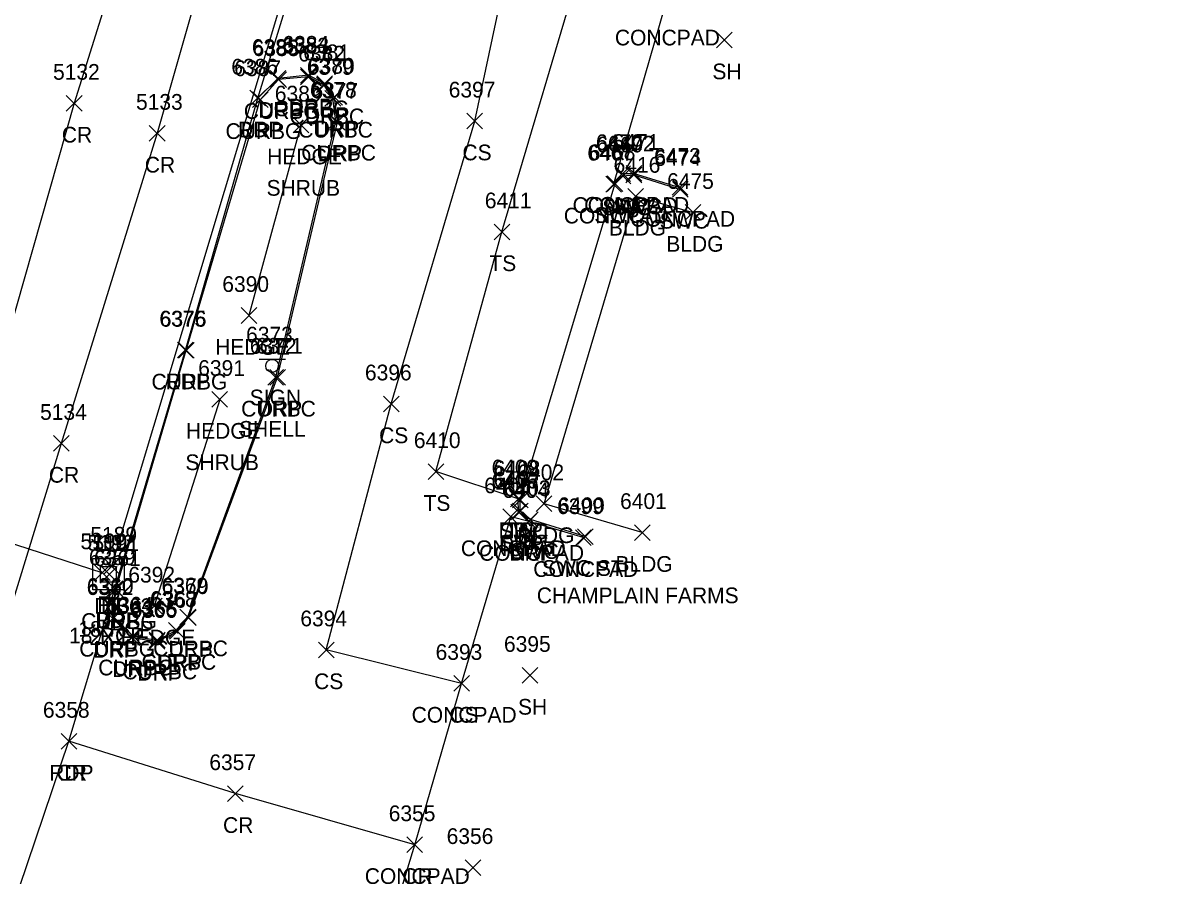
# Model space of a CAD drawing. Extents: x 1462089 to 1464015, y 730534 to 736144.
# Drawn here: x 1462606.1 to 1462752.9, y 731296.2 to 731404.8 of the extents above; entities that cross this region are included whole.
import ezdxf

# ---------------------------------------------------------------- set-up
doc = ezdxf.new("R2010")
doc.units = 0
for name, color, linetype in [('D_A', 7, 'Continuous'), ('D_C', 7, 'Continuous'), ('D_I', 7, 'Continuous'), ('D_TIC', 7, 'Continuous'), ('DCP', 7, 'Continuous'), ('DS', 7, 'Continuous'), ('L_A', 7, 'Continuous'), ('L_C', 7, 'Continuous'), ('L_I', 7, 'Continuous'), ('L_TIC', 7, 'Continuous'), ('LAHR', 7, 'Continuous'), ('LBC', 7, 'Continuous'), ('LELB', 7, 'Continuous'), ('LS', 7, 'Continuous'), ('P_A', 7, 'Continuous'), ('P_I', 7, 'Continuous'), ('P_TIC', 7, 'Continuous'), ('PET', 7, 'Continuous'), ('PRC', 7, 'Continuous'), ('R_A', 7, 'Continuous'), ('R_I', 7, 'Continuous'), ('R_TIC', 7, 'Continuous'), ('RC', 7, 'Continuous'), ('RDP', 7, 'Continuous'), ('RSW', 7, 'Continuous'), ('S_A', 7, 'Continuous'), ('S_C', 7, 'Continuous'), ('S_I', 7, 'Continuous'), ('SSGN', 7, 'Continuous')]:
    doc.layers.add(name, color=color, linetype=linetype)

msp = doc.modelspace()

# ---------------------------------------------------------------- linework, layer by layer
at = {"layer": 'D_TIC'}
for points in [[(1462615.15, 731333.76), (1462617.15, 731335.76)], [(1462617.15, 731333.76), (1462615.15, 731335.76)], [(1462616.03, 731333.54), (1462618.03, 731335.54)], [(1462618.03, 731333.54), (1462616.03, 731335.54)], [(1462616.33, 731334.6), (1462618.33, 731336.6)], [(1462618.33, 731334.6), (1462616.33, 731336.6)]]:
    msp.add_lwpolyline(points, dxfattribs=at)
at = {"layer": 'DCP'}
for points in [[(1462656.86, 731467.04), (1462617.33, 731335.6)], [(1462616.15, 731334.76), (1462550.47, 731356.02)]]:
    msp.add_lwpolyline(points, dxfattribs=at)
at = {"layer": 'DS'}
for p, q in [((1462614.94, 731336.57), (1462618.94, 731336.57)), ((1462614.94, 731332.57), (1462614.94, 731336.57)), ((1462615.94, 731333.57), (1462615.94, 731335.57)), ((1462615.94, 731335.57), (1462617.94, 731335.57)), ((1462617.94, 731335.57), (1462617.94, 731333.57)), ((1462618.94, 731336.57), (1462618.94, 731332.57)), ((1462616.95, 731334.57), (1462616.95, 731334.57)), ((1462616.95, 731334.57), (1462616.95, 731334.57)), ((1462618.94, 731332.57), (1462614.94, 731332.57)), ((1462617.94, 731333.57), (1462615.94, 731333.57))]:
    msp.add_line(p, q, dxfattribs=at)
at = {"layer": 'L_TIC'}
for points in [[(1462694.38, 731401.6), (1462696.38, 731403.6)], [(1462696.38, 731401.6), (1462694.38, 731403.6)], [(1462640.45, 731390.77), (1462642.45, 731392.77)], [(1462642.45, 731390.77), (1462640.45, 731392.77)], [(1462662.59, 731391.28), (1462664.59, 731393.28)], [(1462664.59, 731391.28), (1462662.59, 731393.28)], [(1462681.42, 731384.58), (1462683.42, 731386.58)], [(1462683.42, 731384.58), (1462681.42, 731386.58)], [(1462682.9, 731384.61), (1462684.9, 731386.61)], [(1462684.9, 731384.61), (1462682.9, 731386.61)], [(1462680.29, 731383.24), (1462682.29, 731385.24)], [(1462682.29, 731383.24), (1462680.29, 731385.24)], [(1462680.29, 731383.24), (1462682.29, 731385.24)], [(1462682.29, 731383.24), (1462680.29, 731385.24)], [(1462688.74, 731382.83), (1462690.74, 731384.83)], [(1462690.74, 731382.83), (1462688.74, 731384.83)], [(1462683.09, 731381.7), (1462685.09, 731383.7)], [(1462685.09, 731381.7), (1462683.09, 731383.7)], [(1462690.41, 731379.64), (1462692.41, 731381.64)], [(1462692.41, 731379.64), (1462690.41, 731381.64)], [(1462666.05, 731377.17), (1462668.05, 731379.17)], [(1462668.05, 731377.17), (1462666.05, 731379.17)], [(1462633.83, 731366.52), (1462635.83, 731368.52)], [(1462635.83, 731366.52), (1462633.83, 731368.52)], [(1462630.11, 731355.83), (1462632.11, 731357.83)], [(1462632.11, 731355.83), (1462630.11, 731357.83)], [(1462651.97, 731355.26), (1462653.97, 731357.26)], [(1462653.97, 731355.26), (1462651.97, 731357.26)], [(1462657.66, 731346.64), (1462659.66, 731348.64)], [(1462659.66, 731346.64), (1462657.66, 731348.64)], [(1462668.13, 731343.16), (1462670.13, 731345.16)], [(1462670.13, 731343.16), (1462668.13, 731345.16)], [(1462671.42, 731342.54), (1462673.42, 731344.54)], [(1462673.42, 731342.54), (1462671.42, 731344.54)], [(1462667.18, 731340.88), (1462669.18, 731342.88)], [(1462669.18, 731340.88), (1462667.18, 731342.88)], [(1462667.18, 731340.88), (1462669.18, 731342.88)], [(1462669.18, 731340.88), (1462667.18, 731342.88)], [(1462669.51, 731340.29), (1462671.51, 731342.29)], [(1462671.51, 731340.29), (1462669.51, 731342.29)], [(1462676.41, 731338.23), (1462678.41, 731340.23)], [(1462678.41, 731338.23), (1462676.41, 731340.23)], [(1462683.93, 731338.88), (1462685.93, 731340.88)], [(1462685.93, 731338.88), (1462683.93, 731340.88)], [(1462621.77, 731329.51), (1462623.77, 731331.51)], [(1462623.77, 731329.51), (1462621.77, 731331.51)], [(1462643.69, 731323.94), (1462645.69, 731325.94)], [(1462645.69, 731323.94), (1462643.69, 731325.94)], [(1462669.62, 731320.69), (1462671.62, 731322.69)], [(1462671.62, 731320.69), (1462669.62, 731322.69)], [(1462660.92, 731319.67), (1462662.92, 731321.67)], [(1462662.92, 731319.67), (1462660.92, 731321.67)], [(1462660.92, 731319.67), (1462662.92, 731321.67)], [(1462662.92, 731319.67), (1462660.92, 731321.67)], [(1462654.95, 731299.13), (1462656.95, 731301.13)], [(1462656.95, 731299.13), (1462654.95, 731301.13)], [(1462662.38, 731296.22), (1462664.38, 731298.22)], [(1462664.38, 731296.22), (1462662.38, 731298.22)]]:
    msp.add_lwpolyline(points, dxfattribs=at)
at = {"layer": 'LAHR'}
for points in [[(1462641.45, 731391.77), (1462634.83, 731367.52)], [(1462631.11, 731356.83), (1462622.77, 731330.51)]]:
    msp.add_lwpolyline(points, dxfattribs=at)
at = {"layer": 'LBC'}
msp.add_lwpolyline([(1462684.93, 731339.88), (1462672.42, 731343.54), (1462684.09, 731382.7), (1462691.41, 731380.64)], dxfattribs=at)
at = {"layer": 'LELB'}
for points in [[(1462669.13, 731344.16), (1462658.66, 731347.64), (1462667.05, 731378.17), (1462677.7, 731414.12), (1462689.25, 731456.08)], [(1462661.92, 731320.67), (1462644.69, 731324.94), (1462652.97, 731356.26), (1462663.59, 731392.28), (1462668.66, 731416.05), (1462674.24, 731446.96)]]:
    msp.add_lwpolyline(points, dxfattribs=at)
at = {"layer": 'LS'}
for points in [[(1462687.8, 731406.91), (1462681.29, 731384.24)], [(1462681.29, 731384.24), (1462682.42, 731385.58), (1462683.9, 731385.61), (1462689.74, 731383.83)], [(1462661.6, 731283.5), (1462651.86, 731286.58), (1462655.95, 731300.13), (1462661.92, 731320.67), (1462668.18, 731341.88)], [(1462677.41, 731339.23), (1462670.51, 731341.29), (1462668.18, 731341.88)]]:
    msp.add_lwpolyline(points, dxfattribs=at)
at = {"layer": 'P_TIC'}
for points in [[(1462634.96, 731394.2), (1462636.96, 731396.2)], [(1462636.96, 731394.2), (1462634.96, 731396.2)], [(1462611.57, 731393.54), (1462613.57, 731395.54)], [(1462613.57, 731393.54), (1462611.57, 731395.54)], [(1462622.14, 731389.72), (1462624.14, 731391.72)], [(1462624.14, 731389.72), (1462622.14, 731391.72)], [(1462625.73, 731362.12), (1462627.73, 731364.12)], [(1462627.73, 731362.12), (1462625.73, 731364.12)], [(1462609.92, 731350.23), (1462611.92, 731352.23)], [(1462611.92, 731350.23), (1462609.92, 731352.23)], [(1462616.75, 731331.74), (1462618.75, 731333.74)], [(1462618.75, 731331.74), (1462616.75, 731333.74)], [(1462610.9, 731312.3), (1462612.9, 731314.3)], [(1462612.9, 731312.3), (1462610.9, 731314.3)], [(1462610.9, 731312.3), (1462612.9, 731314.3)], [(1462612.9, 731312.3), (1462610.9, 731314.3)], [(1462632.1, 731305.63), (1462634.1, 731307.63)], [(1462634.1, 731305.63), (1462632.1, 731307.63)], [(1462654.95, 731299.13), (1462656.95, 731301.13)], [(1462656.95, 731299.13), (1462654.95, 731301.13)]]:
    msp.add_lwpolyline(points, dxfattribs=at)
at = {"layer": 'PET'}
msp.add_lwpolyline([(1462581.47, 731216.16), (1462595.42, 731259.35), (1462601.33, 731282.14), (1462611.9, 731313.3), (1462617.75, 731332.74), (1462626.73, 731363.12), (1462635.96, 731395.2), (1462650.7, 731443.13), (1462658.25, 731467.85), (1462666.38, 731494.9), (1462678.49, 731533.96), (1462682, 731542.57), (1462703.33, 731606.12), (1462712.89, 731635.26), (1462724.51, 731674.81), (1462732.57, 731701.31), (1462734.12, 731706.18), (1462734.47, 731705.73), (1462745.24, 731743.48), (1462759.09, 731789.57)], dxfattribs=at)
at = {"layer": 'PRC'}
for points in [[(1462782.02, 731950.47), (1462768.89, 731909.84), (1462760.03, 731877.27), (1462749.82, 731847.72), (1462735.79, 731799.64), (1462732.29, 731789.16), (1462718.71, 731743.61), (1462707.11, 731705.53), (1462694.32, 731660.71), (1462680.69, 731618.48), (1462665.7, 731575.68), (1462653.41, 731528.21), (1462637.72, 731478.42), (1462624.25, 731431.84), (1462612.57, 731394.54), (1462600.92, 731353.76), (1462584.46, 731303.13), (1462565.79, 731242.26), (1462548.64, 731186.3), (1462531.51, 731132.98), (1462517.28, 731085.28)], [(1462793.02, 731947.65), (1462779.18, 731905.95), (1462772.13, 731874.55), (1462759.59, 731843.4), (1462745.8, 731796.52), (1462742.09, 731785.85), (1462729.2, 731739.31), (1462722.15, 731715.56), (1462711.04, 731679.92), (1462704.9, 731658.03), (1462690.28, 731612.58), (1462677.1, 731571.22), (1462663.07, 731525.56), (1462648.8, 731477.5), (1462634.52, 731430.68), (1462623.14, 731390.72), (1462610.92, 731351.23), (1462594.7, 731298.49), (1462575.73, 731238.98), (1462558.6, 731184.66), (1462539.6, 731135.54), (1462521.54, 731083.73), (1462509.35, 731045.03)], [(1462655.95, 731300.13), (1462633.1, 731306.63), (1462611.9, 731313.3)]]:
    msp.add_lwpolyline(points, dxfattribs=at)
at = {"layer": 'R_TIC'}
for points in [[(1462637.52, 731396.7), (1462639.52, 731398.7)], [(1462639.52, 731396.7), (1462637.52, 731398.7)], [(1462641.4, 731396.89), (1462643.4, 731398.89)], [(1462643.4, 731396.89), (1462641.4, 731398.89)], [(1462641.41, 731397.11), (1462643.41, 731399.11)], [(1462643.41, 731397.11), (1462641.41, 731399.11)], [(1462637.6, 731396.56), (1462639.6, 731398.56)], [(1462639.6, 731396.56), (1462637.6, 731398.56)], [(1462637.6, 731396.56), (1462639.6, 731398.56)], [(1462639.6, 731396.56), (1462637.6, 731398.56)], [(1462643.42, 731395.87), (1462645.42, 731397.87)], [(1462645.42, 731395.87), (1462643.42, 731397.87)], [(1462643.49, 731396.03), (1462645.49, 731398.03)], [(1462645.49, 731396.03), (1462643.49, 731398.03)], [(1462634.96, 731394.2), (1462636.96, 731396.2)], [(1462636.96, 731394.2), (1462634.96, 731396.2)], [(1462635.27, 731394), (1462637.27, 731396)], [(1462637.27, 731394), (1462635.27, 731396)], [(1462644.52, 731394.17), (1462646.52, 731396.17)], [(1462646.52, 731394.17), (1462644.52, 731396.17)], [(1462644.74, 731394.31), (1462646.74, 731396.31)], [(1462646.74, 731394.31), (1462644.74, 731396.31)], [(1462644.91, 731391.25), (1462646.91, 731393.25)], [(1462646.91, 731391.25), (1462644.91, 731393.25)], [(1462645.1, 731391.14), (1462647.1, 731393.14)], [(1462647.1, 731391.14), (1462645.1, 731393.14)], [(1462681.48, 731384.29), (1462683.48, 731386.29)], [(1462683.48, 731384.29), (1462681.48, 731386.29)], [(1462682.86, 731384.41), (1462684.86, 731386.41)], [(1462684.86, 731384.41), (1462682.86, 731386.41)], [(1462680.47, 731383.31), (1462682.47, 731385.31)], [(1462682.47, 731383.31), (1462680.47, 731385.31)], [(1462688.79, 731382.58), (1462690.79, 731384.58)], [(1462690.79, 731382.58), (1462688.79, 731384.58)], [(1462625.84, 731362.09), (1462627.84, 731364.09)], [(1462627.84, 731362.09), (1462625.84, 731364.09)], [(1462637.25, 731358.65), (1462639.25, 731360.65)], [(1462639.25, 731358.65), (1462637.25, 731360.65)], [(1462637.48, 731358.66), (1462639.48, 731360.66)], [(1462639.48, 731358.66), (1462637.48, 731360.66)], [(1462668.13, 731343.16), (1462670.13, 731345.16)], [(1462670.13, 731343.16), (1462668.13, 731345.16)], [(1462668.39, 731343.04), (1462670.39, 731345.04)], [(1462670.39, 731343.04), (1462668.39, 731345.04)], [(1462668.18, 731341.49), (1462670.18, 731343.49)], [(1462670.18, 731341.49), (1462668.18, 731343.49)], [(1462668.39, 731341.6), (1462670.39, 731343.6)], [(1462670.39, 731341.6), (1462668.39, 731343.6)], [(1462669.51, 731340.29), (1462671.51, 731342.29)], [(1462671.51, 731340.29), (1462669.51, 731342.29)], [(1462669.69, 731340.52), (1462671.69, 731342.52)], [(1462671.69, 731340.52), (1462669.69, 731342.52)], [(1462676.67, 731338.36), (1462678.67, 731340.36)], [(1462678.67, 731338.36), (1462676.67, 731340.36)], [(1462616.75, 731331.74), (1462618.75, 731333.74)], [(1462618.75, 731331.74), (1462616.75, 731333.74)], [(1462616.87, 731331.61), (1462618.87, 731333.61)], [(1462618.87, 731331.61), (1462616.87, 731333.61)], [(1462616.52, 731327.93), (1462618.52, 731329.93)], [(1462618.52, 731327.93), (1462616.52, 731329.93)], [(1462616.64, 731328.08), (1462618.64, 731330.08)], [(1462618.64, 731328.08), (1462616.64, 731330.08)], [(1462616.64, 731328.08), (1462618.64, 731330.08)], [(1462618.64, 731328.08), (1462616.64, 731330.08)], [(1462626.05, 731328.13), (1462628.05, 731330.13)], [(1462628.05, 731328.13), (1462626.05, 731330.13)], [(1462626.12, 731328.05), (1462628.12, 731330.05)], [(1462628.12, 731328.05), (1462626.12, 731330.05)], [(1462624.57, 731326.41), (1462626.57, 731328.41)], [(1462626.57, 731326.41), (1462624.57, 731328.41)], [(1462624.72, 731326.3), (1462626.72, 731328.3)], [(1462626.72, 731326.3), (1462624.72, 731328.3)], [(1462618.92, 731325.5), (1462620.92, 731327.5)], [(1462620.92, 731325.5), (1462618.92, 731327.5)], [(1462619.05, 731325.69), (1462621.05, 731327.69)], [(1462621.05, 731325.69), (1462619.05, 731327.69)], [(1462622.13, 731325.02), (1462624.13, 731327.02)], [(1462624.13, 731325.02), (1462622.13, 731327.02)], [(1462622.14, 731325.19), (1462624.14, 731327.19)], [(1462624.14, 731325.19), (1462622.14, 731327.19)]]:
    msp.add_lwpolyline(points, dxfattribs=at)
at = {"layer": 'RC'}
for points in [[(1462617.64, 731329.08), (1462620.05, 731326.69), (1462623.14, 731326.19), (1462625.57, 731327.41), (1462627.05, 731329.13), (1462638.25, 731359.65), (1462645.91, 731392.25), (1462645.52, 731395.17), (1462644.42, 731396.87), (1462642.4, 731397.89), (1462638.6, 731397.56)], [(1462617.64, 731329.08), (1462617.87, 731332.61), (1462626.84, 731363.09), (1462636.27, 731395), (1462638.6, 731397.56)]]:
    msp.add_lwpolyline(points, dxfattribs=at)
at = {"layer": 'RDP'}
for points in [[(1462617.75, 731332.74), (1462617.52, 731328.93), (1462619.92, 731326.5), (1462623.13, 731326.02), (1462625.72, 731327.3), (1462627.12, 731329.05), (1462638.48, 731359.66), (1462646.1, 731392.14), (1462645.74, 731395.31), (1462644.49, 731397.03), (1462642.41, 731398.11), (1462638.52, 731397.7), (1462635.96, 731395.2)], [(1462670.51, 731341.29), (1462669.18, 731342.49), (1462669.13, 731344.16)]]:
    msp.add_lwpolyline(points, dxfattribs=at)
at = {"layer": 'RSW'}
msp.add_lwpolyline([(1462677.67, 731339.36), (1462670.69, 731341.52), (1462669.39, 731342.6), (1462669.39, 731344.04), (1462681.47, 731384.31), (1462682.48, 731385.29), (1462683.86, 731385.41), (1462689.79, 731383.58)], dxfattribs=at)
at = {"layer": 'SSGN'}
for p, q in [((1462636.15, 731361.94), (1462639.48, 731361.94)), ((1462637.8, 731361.1), (1462637.8, 731361.1))]:
    msp.add_line(p, q, dxfattribs=at)
msp.add_circle((1462637.8, 731361.1), 0.833, dxfattribs=at)

# ---------------------------------------------------------------- texts
at = {"layer": 'D_A'}
for s, p in [('P', (1462616.7, 731330.6)), ('DIB', (1462615.13, 731329.54)), ('P', (1462615.53, 731329.76)), ('DI', (1462616, 731329.57))]:
    msp.add_text(s, height=2, dxfattribs=at).set_placement(p)
at = {"layer": 'D_C'}
for s, p in [('18"RCP', (1462613.1, 731326.6)), ('18"RCP', (1462611.92, 731325.76)), ('2X2', (1462614.52, 731325.57))]:
    msp.add_text(s, height=2, dxfattribs=at).set_placement(p)
at = {"layer": 'D_I'}
for s, p in [('5189', (1462614.63, 731338.6)), ('5190', (1462613.37, 731337.76)), ('5192', (1462614.25, 731337.57)), ('5191', (1462614.9, 731337.54))]:
    msp.add_text(s, height=2, dxfattribs=at).set_placement(p)
at = {"layer": 'L_A'}
for s, p in [('CONCPAD', (1462681.45, 731401.91)), ('CONCPAD', (1462681.45, 731401.91)), ('SH', (1462693.87, 731397.6)), ('HEDGE', (1462637.15, 731386.77)), ('CS', (1462662.03, 731387.28)), ('CONCPAD', (1462676.06, 731380.58)), ('CONCPAD', (1462677.54, 731380.61)), ('CONCPAD', (1462674.94, 731379.24)), ('CONCPAD', (1462674.94, 731379.24)), ('BLDG', (1462680.68, 731377.7)), ('CONCPAD', (1462683.39, 731378.83)), ('BLDG', (1462688, 731375.64)), ('TS', (1462665.46, 731373.17)), ('HEDGE', (1462630.54, 731362.52)), ('HEDGE', (1462626.81, 731351.83)), ('CS', (1462651.41, 731351.26)), ('TS', (1462657.07, 731342.64)), ('TS', (1462667.54, 731339.16)), ('BLDG', (1462669.01, 731338.54)), ('CONCPAD', (1462661.83, 731336.88)), ('CONCPAD', (1462661.83, 731336.88)), ('CONCPAD', (1462664.15, 731336.29)), ('BLDG', (1462681.52, 731334.88)), ('CONCPAD', (1462671.05, 731334.23)), ('HEDGE', (1462618.48, 731325.51)), ('CS', (1462643.13, 731319.94)), ('SH', (1462669.11, 731316.69)), ('CONCPAD', (1462655.56, 731315.67)), ('CS', (1462660.36, 731315.67)), ('CONCPAD', (1462649.59, 731295.13))]:
    msp.add_text(s, height=2, dxfattribs=at).set_placement(p)
at = {"layer": 'L_C'}
for s, p in [('SHRUB', (1462637.08, 731382.77)), ('SHRUB', (1462626.74, 731347.83)), ('CHAMPLAIN FARMS', (1462671.5, 731330.88))]:
    msp.add_text(s, height=2, dxfattribs=at).set_placement(p)
at = {"layer": 'L_I'}
for s, p in [('6397', (1462660.28, 731395.28)), ('6389', (1462638.13, 731394.77)), ('6470', (1462679.03, 731388.58)), ('6471', (1462681.16, 731388.61)), ('6467', (1462677.94, 731387.24)), ('6467', (1462677.94, 731387.24)), ('6473', (1462686.44, 731386.83)), ('6416', (1462681.29, 731385.7)), ('6475', (1462688.1, 731383.64)), ('6411', (1462664.88, 731381.17)), ('6390', (1462631.44, 731370.52)), ('6391', (1462628.37, 731359.83)), ('6396', (1462649.61, 731359.26)), ('6410', (1462655.84, 731350.64)), ('6409', (1462665.74, 731347.16)), ('6402', (1462669.03, 731346.54)), ('6405', (1462664.8, 731344.88)), ('6405', (1462664.8, 731344.88)), ('6404', (1462667.12, 731344.29)), ('6399', (1462674.09, 731342.23)), ('6401', (1462682.11, 731342.88)), ('6392', (1462619.47, 731333.51)), ('6394', (1462641.38, 731327.94)), ('6395', (1462667.32, 731324.69)), ('6393', (1462658.61, 731323.67)), ('6393', (1462658.61, 731323.67)), ('6355', (1462652.64, 731303.13)), ('6356', (1462660.02, 731300.22))]:
    msp.add_text(s, height=2, dxfattribs=at).set_placement(p)
at = {"layer": 'P_A'}
for s, p in [('CR', (1462611, 731389.54)), ('RDP', (1462633.44, 731390.2)), ('CR', (1462621.57, 731385.72)), ('RDP', (1462624.21, 731358.12)), ('CR', (1462609.35, 731346.23)), ('RDP', (1462615.24, 731327.74)), ('RDP', (1462609.39, 731308.3)), ('CR', (1462610.33, 731308.3)), ('CR', (1462631.53, 731301.63)), ('CR', (1462654.38, 731295.13))]:
    msp.add_text(s, height=2, dxfattribs=at).set_placement(p)
at = {"layer": 'P_I'}
for s, p in [('6386', (1462632.59, 731398.2)), ('5132', (1462609.88, 731397.54)), ('5133', (1462620.45, 731393.72)), ('6375', (1462623.42, 731366.12)), ('5134', (1462608.23, 731354.23)), ('6359', (1462614.44, 731335.74)), ('6358', (1462608.59, 731316.3)), ('6358', (1462608.59, 731316.3)), ('6357', (1462629.79, 731309.63)), ('6355', (1462652.64, 731303.13))]:
    msp.add_text(s, height=2, dxfattribs=at).set_placement(p)
at = {"layer": 'R_A'}
for s, p in [('CURBG', (1462634.18, 731392.56)), ('CURBC', (1462634.18, 731392.56)), ('DRP', (1462636.01, 731392.7)), ('CURBC', (1462637.98, 731392.89)), ('DRP', (1462639.9, 731393.11)), ('CURBC', (1462640, 731391.87)), ('DRP', (1462641.98, 731392.03)), ('CURBG', (1462631.85, 731390)), ('DRP', (1462633.44, 731390.2)), ('CURBC', (1462641.11, 731390.17)), ('DRP', (1462643.23, 731390.31)), ('CURBC', (1462641.5, 731387.25)), ('DRP', (1462643.59, 731387.14)), ('SWC', (1462681.22, 731380.41)), ('SWC', (1462678.83, 731379.31)), ('SWC', (1462679.84, 731380.29)), ('SWC', (1462687.15, 731378.58)), ('CURBG', (1462622.42, 731358.09)), ('CURBC', (1462633.84, 731354.65)), ('DRP', (1462635.97, 731354.66)), ('DRP', (1462666.62, 731339.16)), ('SWC', (1462666.75, 731339.04)), ('SWC', (1462666.75, 731337.6)), ('DRP', (1462666.67, 731337.49)), ('SWC', (1462668.05, 731336.52)), ('DRP', (1462668, 731336.29)), ('SWC ST', (1462672.17, 731334.36)), ('CURBG', (1462613.46, 731327.61)), ('DRP', (1462615.24, 731327.74)), ('CURBG', (1462613.22, 731324.08)), ('CURBC', (1462613.22, 731324.08)), ('DRP', (1462615.01, 731323.93)), ('CURBC', (1462622.64, 731324.13)), ('DRP', (1462624.61, 731324.05)), ('CURBC', (1462615.64, 731321.69)), ('CURBC', (1462621.15, 731322.41)), ('DRP', (1462623.21, 731322.3)), ('DRP', (1462617.41, 731321.5)), ('CURBC', (1462618.72, 731321.19)), ('DRP', (1462620.62, 731321.02))]:
    msp.add_text(s, height=2, dxfattribs=at).set_placement(p)
at = {"layer": 'R_I'}
for s, p in [('6384', (1462639.1, 731401.11)), ('6385', (1462635.21, 731400.7)), ('6388', (1462635.3, 731400.56)), ('6388', (1462635.3, 731400.56)), ('6383', (1462639.09, 731400.89)), ('6382', (1462641.11, 731399.87)), ('6381', (1462641.75, 731400.03)), ('6386', (1462632.59, 731398.2)), ('6387', (1462632.96, 731398)), ('6379', (1462642.21, 731398.17)), ('6380', (1462642.35, 731398.31)), ('6378', (1462642.61, 731395.25)), ('6377', (1462642.8, 731395.14)), ('6469', (1462679.11, 731388.29)), ('6472', (1462680.55, 731388.41)), ('6468', (1462678.12, 731387.31)), ('6474', (1462686.48, 731386.58)), ('6376', (1462623.48, 731366.09)), ('6372', (1462634.95, 731362.65)), ('6371', (1462635.74, 731362.66)), ('6409', (1462665.74, 731347.16)), ('6408', (1462666.01, 731347.04)), ('6406', (1462665.74, 731345.49)), ('6407', (1462666.01, 731345.6)), ('6404', (1462667.12, 731344.29)), ('6403', (1462667.3, 731344.52)), ('6400', (1462674.2, 731342.36)), ('6359', (1462614.44, 731335.74)), ('6361', (1462615.09, 731335.61)), ('6362', (1462614.17, 731331.93)), ('6360', (1462614.19, 731332.08)), ('6360', (1462614.19, 731332.08)), ('6369', (1462623.69, 731332.13)), ('6370', (1462623.73, 731332.05)), ('6363', (1462616.57, 731329.5)), ('6364', (1462616.7, 731329.69)), ('6366', (1462619.72, 731329.02)), ('6365', (1462619.79, 731329.19)), ('6368', (1462622.22, 731330.41)), ('6367', (1462622.36, 731330.3))]:
    msp.add_text(s, height=2, dxfattribs=at).set_placement(p)
at = {"layer": 'S_A'}
msp.add_text('SIGN', height=2, dxfattribs=at).set_placement((1462634.93, 731356.08))
at = {"layer": 'S_C'}
msp.add_text('SHELL', height=2, dxfattribs=at).set_placement((1462633.57, 731352.08))
at = {"layer": 'S_I'}
msp.add_text('6373', height=2, dxfattribs=at).set_placement((1462634.47, 731364.08))

doc.saveas('drawing.dxf')
